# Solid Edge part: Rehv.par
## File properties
Author: Türk
Template: Iso Part.par
Last saved by: Türk
Revision: 23
Application: Solid Edge
Accuracy: 0,990
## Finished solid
Body 1: sheet body, 2 faces, 72 edges, 72 vertices.
  Faces by surface: plane 2
  Edges by curve: line 40, circle 24, spline 8
Body 2: solid body, 36 faces, 36 edges, 0 vertices.
  Faces by surface: torus 12, cylinder 10, plane 10, spun 4
  Edges by curve: circle 36
Bounding box of the edges (mm; curved faces can reach further): 233.000 x 602.200 x 602.624, from (-150, -301.1, -301.312) to (83, 301.1, 301.312).
Cylindrical faces by radius (mm): R216.1 x2, R226.1 x4, R239.1 x2, R291.1019 x1, R301.1 x1
Toroidal faces (ring radius, tube radius in mm): R220.1 r4 x4, R222.1 r4 x2, R231.1 r8 x2, R273.3411 r15 x2, R273.3411 r25 x2
Planar faces by outward normal: +x 5, -x 5
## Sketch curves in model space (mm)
line (-41.1867, 0, 291.1019) -> (-41, 0, 291.1019)
line (-25.8133, 0, 291.1019) -> (-26, 0, 291.1019)
spline (116.1068, 0, 298.6599) -> (116.4318, 0, 298.5724) -> (116.7543, 0, 298.484)
spline (117.9512, 0, 298.6599) -> (118.2763, 0, 298.5724) -> (118.5988, 0, 298.484)
spline (-116.1068, 0, 298.6599) -> (-116.4318, 0, 298.5724) -> (-116.7543, 0, 298.484)
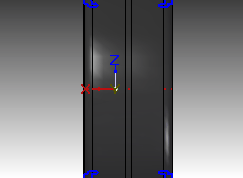
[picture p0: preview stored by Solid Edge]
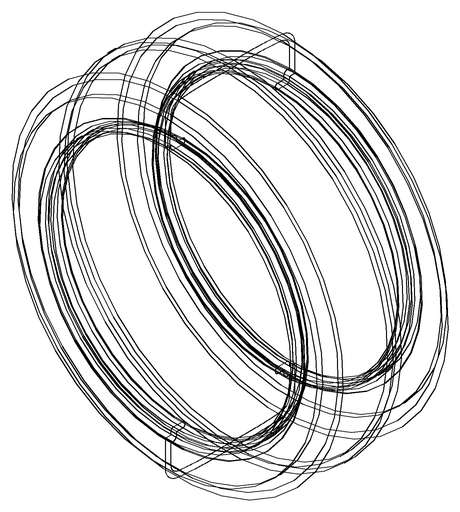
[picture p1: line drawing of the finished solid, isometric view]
